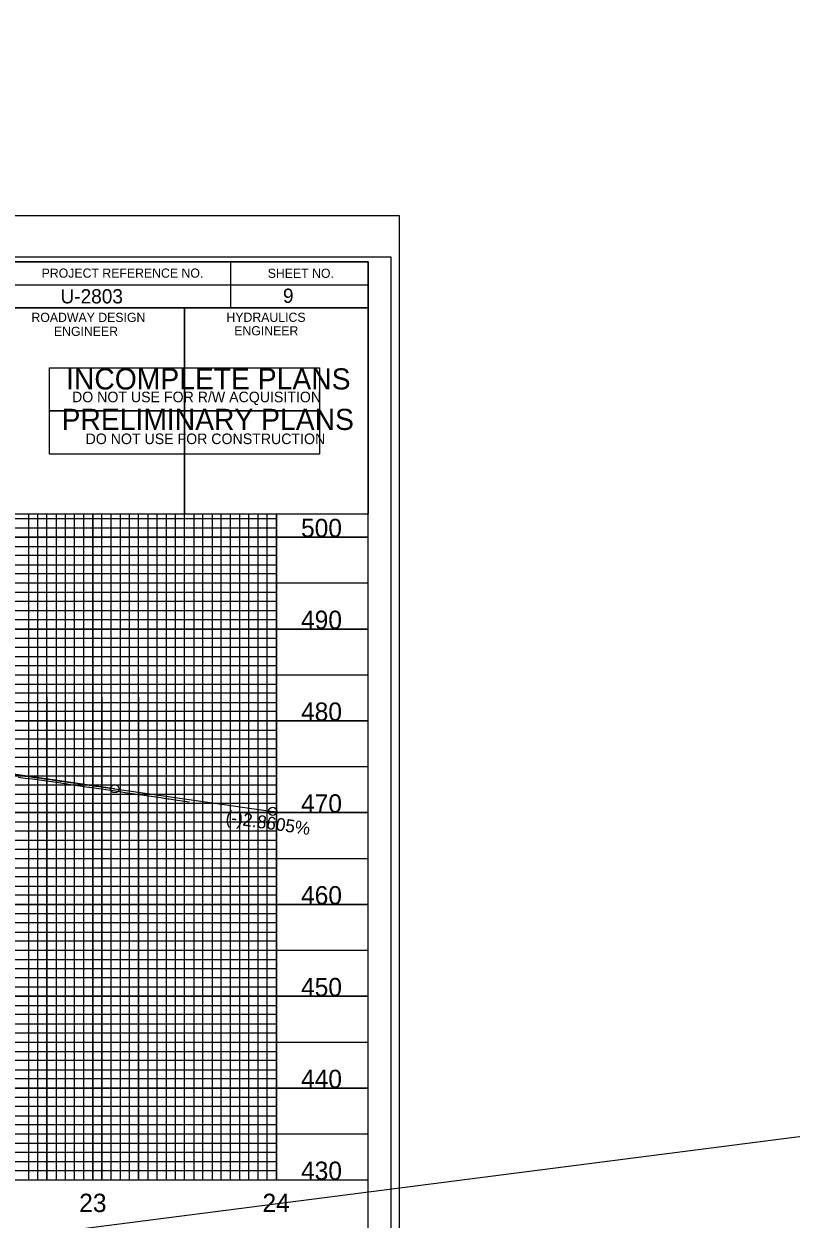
# Model space of a CAD drawing. Extents: x 571503 to 593215, y -77195 to -51828.
# Drawn here: x 582985 to 583403, y -53130 to -52479 of the extents above; entities that cross this region are included whole.
import ezdxf

# ---------------------------------------------------------------- set-up
doc = ezdxf.new("R2010")
doc.units = 0
for name, color, linetype in [('Exist Vertical Profile Ground Line', 7, 'Continuous'), ('Exist Vertical Profile Horizontal Axis Label Major', 7, 'Continuous'), ('Exist Vertical Profile Vertical Axis Label', 7, 'Continuous'), ('Prop PFL Text', 7, 'Continuous'), ('Prop Vertical Profile Curve Label', 7, 'Continuous'), ('Prop Vertical Profile Grade', 7, 'Continuous'), ('Prop Vertical Profile Grade Label', 7, 'Continuous'), ('Prop VPI Label', 7, 'Continuous'), ('Sheet Clip Boundary CELL', 7, 'Continuous'), ('Sheet Data Field CELL', 7, 'Continuous'), ('Sheet DOT Grid CELL', 7, 'Continuous'), ('Sheet Plot Border Inside CELL', 7, 'Continuous'), ('Sheet Plot Border Outside CELL', 7, 'Continuous'), ('Sheet Profile CELL', 7, 'Continuous'), ('Sheet Profile Grid Major CELL', 7, 'Continuous'), ('Sheet Profile Grid Middle CELL', 7, 'Continuous'), ('Sheet Profile Grid Minor CELL', 7, 'Continuous'), ('Sheet Sticker Incomplete CELL', 7, 'Continuous'), ('Sheet Sticker Preliminary CELL', 7, 'Continuous')]:
    doc.layers.add(name, color=color, linetype=linetype)

msp = doc.modelspace()

# ---------------------------------------------------------------- linework, layer by layer
at = {"layer": 'Exist Vertical Profile Ground Line'}
msp.add_lwpolyline([(582981.88, -52889.3), (582985.76, -52889.84), (582989.64, -52890.37), (582993.53, -52890.91), (582997.41, -52891.45), (583000.06, -52891.82), (583001.3, -52892), (583005.18, -52892.55), (583007.78, -52892.92), (583008.24, -52892.98), (583008.57, -52893.03), (583009.07, -52893.1), (583012.95, -52893.66), (583016.83, -52894.22), (583020.36, -52894.73), (583020.72, -52894.78), (583024.6, -52895.35), (583028.49, -52895.92), (583032, -52896.44), (583032.04, -52896.44), (583032.37, -52896.49), (583036.26, -52897.06), (583040.14, -52897.64), (583044.02, -52898.21), (583047.91, -52898.79), (583051.79, -52899.36), (583055.68, -52899.94), (583059.56, -52900.52), (583061.49, -52900.81), (583063.45, -52901.1), (583063.87, -52901.17), (583063.95, -52901.18), (583064, -52901.19), (583065.4, -52901.38), (583067.33, -52901.66), (583071.21, -52902.22), (583075.1, -52902.79)], dxfattribs=at)
at = {"layer": 'Prop PFL Text'}
msp.add_line((571799.62, -54572.45), (593215.36, -51828.37), dxfattribs=at)
at = {"layer": 'Prop Vertical Profile Curve Label'}
for centre in [(583034.51, -52895.68), (583120.51, -52907.98)]:
    msp.add_circle(centre, 2.25, dxfattribs=at)
at = {"layer": 'Prop Vertical Profile Grade'}
msp.add_line((583034.51, -52895.68), (583120.51, -52907.98), dxfattribs=at)
for points in [[(582684.51, -52851.36), (582691.51, -52852.13), (582698.51, -52852.91), (582705.51, -52853.7), (582712.51, -52854.48), (582719.51, -52855.28), (582726.51, -52856.07), (582733.51, -52856.87), (582740.51, -52857.68), (582747.51, -52858.49), (582754.51, -52859.31), (582761.51, -52860.13), (582768.51, -52860.95), (582775.51, -52861.78), (582782.51, -52862.61), (582789.51, -52863.45), (582796.51, -52864.29), (582803.51, -52865.14), (582810.51, -52865.99), (582817.51, -52866.85), (582824.51, -52867.71), (582831.51, -52868.58), (582838.51, -52869.45), (582845.51, -52870.32), (582852.51, -52871.2), (582859.51, -52872.08), (582866.51, -52872.97), (582873.51, -52873.87), (582880.51, -52874.76), (582887.51, -52875.67), (582894.51, -52876.57), (582901.51, -52877.49), (582908.51, -52878.4), (582915.51, -52879.32), (582922.51, -52880.25), (582929.51, -52881.18), (582936.51, -52882.11), (582943.51, -52883.05), (582950.51, -52884), (582957.51, -52884.94), (582964.51, -52885.9), (582971.51, -52886.85), (582978.51, -52887.82), (582985.51, -52888.78), (582992.51, -52889.75), (582999.51, -52890.73), (583006.51, -52891.71), (583013.51, -52892.7), (583020.51, -52893.69), (583027.51, -52894.68), (583034.51, -52895.68)], [(583120.51, -52907.98), (583122.11, -52908.21), (583122.7, -52908.29)]]:
    msp.add_spline(points, degree=3, dxfattribs=at)
at = {"layer": 'Prop VPI Label'}
msp.add_line((583034.51, -52895.68), (582862.23, -52871.04), dxfattribs=at)
at = {"layer": 'Sheet Clip Boundary CELL'}
msp.add_lwpolyline([(581722.51, -52608.7), (581722.51, -53108.7), (583122.51, -53108.7), (583122.51, -52746.25), (582972.46, -52746.25), (582972.46, -52608.7)], close=True, dxfattribs=at)
at = {"layer": 'Sheet DOT Grid CELL'}
for p, q in [((583022.51, -53108.7), (583022.51, -52746.25)), ((583022.51, -53108.7), (583022.51, -52746.25)), ((583072.51, -53108.7), (583072.51, -52746.25)), ((583072.51, -53108.7), (583072.51, -52746.25)), ((583122.51, -53108.7), (583122.51, -52746.25)), ((583122.51, -53108.7), (583122.51, -52746.25)), ((583172.51, -53108.7), (583172.51, -52746.25)), ((581672.51, -52758.7), (583172.51, -52758.7)), ((583172.51, -52758.7), (581672.51, -52758.7)), ((581672.51, -52808.7), (583172.51, -52808.7)), ((583172.51, -52808.7), (581672.51, -52808.7)), ((581672.51, -52858.7), (583172.51, -52858.7)), ((583172.51, -52858.7), (581672.51, -52858.7)), ((581672.51, -52908.7), (583172.51, -52908.7)), ((583172.51, -52908.7), (581672.51, -52908.7)), ((581672.51, -52958.7), (583172.51, -52958.7)), ((583172.51, -52958.7), (581672.51, -52958.7)), ((581672.51, -53008.7), (583172.51, -53008.7)), ((583172.51, -53008.7), (581672.51, -53008.7)), ((581672.51, -53058.7), (583172.51, -53058.7)), ((583172.51, -53058.7), (581672.51, -53058.7))]:
    msp.add_line(p, q, dxfattribs=at)
at = {"layer": 'Sheet Plot Border Inside CELL'}
msp.add_lwpolyline([(581518.51, -53661.25), (583185.01, -53661.25), (583185.01, -52606.15), (581518.51, -52606.15)], close=True, dxfattribs=at)
at = {"layer": 'Sheet Plot Border Outside CELL'}
msp.add_lwpolyline([(581505.51, -53683.7), (583189.51, -53683.7), (583189.51, -52583.7), (581505.51, -52583.7)], close=True, dxfattribs=at)
at = {"layer": 'Sheet Profile CELL'}
for p, q in [((583189.51, -52583.7), (581505.51, -52583.7)), ((583097.51, -52608.75), (583097.51, -52633.75)), ((582972.46, -52621.25), (583172.51, -52621.25)), ((583072.51, -52633.75), (583072.51, -52746.2)), ((581672.51, -53108.7), (583172.51, -53108.7))]:
    msp.add_line(p, q, dxfattribs=at)
for points in [[(583172.51, -52608.7), (581672.51, -52608.7), (581672.51, -53658.7), (583172.51, -53658.7)], [(582972.46, -52608.7), (583172.51, -52608.7), (583172.51, -52633.75), (582972.46, -52633.75)], [(582972.46, -52633.75), (583072.51, -52633.75), (583072.51, -52746.25), (582972.46, -52746.25)], [(583072.51, -52633.75), (583172.51, -52633.75), (583172.51, -52746.25), (583072.51, -52746.25)]]:
    msp.add_lwpolyline(points, close=True, dxfattribs=at)
at = {"layer": 'Sheet Profile Grid Major CELL'}
for points in [[(582522.51, -53108.7), (582572.51, -53108.7), (582572.51, -52608.7), (582622.51, -52608.7), (582622.51, -53108.7), (582672.51, -53108.7), (582672.51, -52608.7), (582722.51, -52608.7), (582722.51, -53108.7), (582772.51, -53108.7), (582772.51, -52608.7), (582822.51, -52608.7), (582822.51, -53108.7), (582872.51, -53108.7), (582872.51, -52608.7), (582922.51, -52608.7), (582922.51, -53108.7), (582972.51, -53108.7), (582972.51, -52608.7), (582998.81, -52608.7)], [(582972.51, -52708.7), (581672.51, -52708.7), (581672.51, -52758.7), (583172.51, -52758.7)], [(583022.51, -52746.25), (583022.51, -53108.7), (583072.51, -53108.7), (583072.51, -53108.7), (583072.51, -52746.25)], [(583122.51, -52746.25), (583122.51, -53108.7), (583172.51, -53108.7), (583172.51, -52758.7)], [(583172.51, -52808.7), (581672.51, -52808.7), (581672.51, -52858.7), (583172.51, -52858.7)], [(583172.51, -52908.7), (581672.51, -52908.7), (581672.51, -52958.7), (583172.51, -52958.7)], [(583172.51, -53008.7), (581672.51, -53008.7), (581672.51, -53008.7), (581672.51, -53058.7), (583172.51, -53058.7)]]:
    msp.add_lwpolyline(points, dxfattribs=at)
at = {"layer": 'Sheet Profile Grid Middle CELL'}
for points in [[(582497.51, -52608.7), (582547.51, -52608.7), (582547.51, -53108.7), (582597.51, -53108.7), (582597.51, -52608.7), (582647.51, -52608.7), (582647.51, -53108.7), (582697.51, -53108.7), (582697.51, -52608.7), (582747.51, -52608.7), (582747.51, -53108.7), (582797.51, -53108.7), (582797.51, -52608.7), (582847.51, -52608.7), (582847.51, -53108.7), (582897.51, -53108.7), (582897.51, -52608.7), (582947.51, -52608.7), (582947.51, -53108.7), (582997.51, -53108.7), (582997.51, -52746.25)], [(582997.51, -52845.9), (582997.51, -53108.7), (583047.51, -53108.7), (583047.51, -52746.25)], [(583047.51, -52845.9), (583047.51, -53108.7), (583097.51, -53108.7), (583097.51, -52746.25)], [(583172.51, -52783.7), (581672.51, -52783.7), (581672.51, -52833.7), (582997.51, -52833.7)], [(582997.51, -52833.7), (583172.51, -52833.7)], [(583172.51, -52883.7), (581672.51, -52883.7), (581672.51, -52933.7), (583172.51, -52933.7)], [(583172.51, -52983.7), (581672.51, -52983.7), (581672.51, -53033.7), (583172.51, -53033.7)], [(583172.51, -53083.7), (581672.51, -53083.7)]]:
    msp.add_lwpolyline(points, dxfattribs=at)
at = {"layer": 'Sheet Profile Grid Minor CELL'}
for p, q in [((583122.51, -52748.7), (581722.51, -52748.7)), ((583122.51, -52753.7), (581722.51, -52753.7)), ((581722.51, -52763.7), (583122.51, -52763.7)), ((583122.51, -52768.7), (581722.51, -52768.7)), ((581722.51, -52773.7), (583122.51, -52773.7)), ((583122.51, -52793.7), (581722.51, -52793.7)), ((581722.51, -52798.7), (583122.51, -52798.7)), ((583122.51, -52818.7), (581722.51, -52818.7)), ((581722.51, -52823.7), (583122.51, -52823.7)), ((583122.51, -52843.7), (581722.51, -52843.7)), ((581722.51, -52848.7), (583122.51, -52848.7)), ((583122.51, -52853.7), (581722.51, -52853.7)), ((581722.51, -52863.7), (583122.51, -52863.7)), ((583122.51, -52868.7), (581722.51, -52868.7)), ((581722.51, -52873.7), (583122.51, -52873.7)), ((583122.51, -52878.7), (581722.51, -52878.7)), ((581722.51, -52888.7), (583122.51, -52888.7)), ((583122.51, -52893.7), (581722.51, -52893.7)), ((581722.51, -52898.7), (583122.51, -52898.7)), ((583122.51, -52903.7), (581722.51, -52903.7)), ((581722.51, -52913.7), (583122.51, -52913.7)), ((583122.51, -52918.7), (581722.51, -52918.7)), ((581722.51, -52923.7), (583122.51, -52923.7)), ((583122.51, -52928.7), (581722.51, -52928.7)), ((581722.51, -52938.7), (583122.51, -52938.7)), ((583122.51, -52943.7), (581722.51, -52943.7)), ((581722.51, -52948.7), (583122.51, -52948.7)), ((583122.51, -52953.7), (581722.51, -52953.7)), ((581722.51, -52963.7), (583122.51, -52963.7)), ((583122.51, -52968.7), (581722.51, -52968.7)), ((581722.51, -52973.7), (583122.51, -52973.7)), ((583122.51, -52978.7), (581722.51, -52978.7)), ((581722.51, -52988.7), (583122.51, -52988.7)), ((583122.51, -52993.7), (581722.51, -52993.7)), ((583122.51, -52998.7), (581722.51, -52998.7)), ((583122.51, -53003.7), (581722.51, -53003.7)), ((581722.51, -53013.7), (583122.51, -53013.7)), ((583122.51, -53018.7), (581722.51, -53018.7)), ((581722.51, -53023.7), (583122.51, -53023.7)), ((583122.51, -53028.7), (581722.51, -53028.7)), ((581722.51, -53038.7), (583122.51, -53038.7)), ((583122.51, -53043.7), (581722.51, -53043.7)), ((581722.51, -53048.7), (583122.51, -53048.7)), ((583122.51, -53053.7), (581722.51, -53053.7)), ((581722.51, -53063.7), (583122.51, -53063.7)), ((583122.51, -53068.7), (581722.51, -53068.7)), ((581722.51, -53073.7), (583122.51, -53073.7)), ((583122.51, -53078.7), (581722.51, -53078.7)), ((581722.51, -53088.7), (583122.51, -53088.7)), ((583122.51, -53093.7), (581722.51, -53093.7)), ((581722.51, -53098.7), (583122.51, -53098.7))]:
    msp.add_line(p, q, dxfattribs=at)
for points in [[(582987.51, -52746.25), (582987.51, -53108.7), (582992.51, -53108.7), (582992.51, -52746.25)], [(583002.51, -52746.25), (583002.51, -53108.7), (583002.51, -53108.7), (583007.51, -53108.7), (583012.51, -53108.7), (583012.51, -52746.25)], [(583007.51, -52746.25), (583007.51, -53108.7)], [(583017.51, -52746.25), (583017.41, -53108.65), (583022.41, -53108.65), (583027.51, -53108.7), (583027.51, -52746.25)], [(583027.51, -52845.9), (583027.51, -53108.7), (583032.51, -53108.7), (583032.51, -52746.25)], [(583037.51, -52746.25), (583037.51, -53108.7), (583042.51, -53108.7), (583042.51, -52746.25)], [(583052.51, -52746.25), (583052.51, -53108.7), (583057.51, -53108.7), (583057.51, -52746.25)], [(583062.51, -52746.25), (583062.51, -53108.7), (583067.51, -53108.7), (583067.51, -52746.25)], [(583077.51, -52746.25), (583077.51, -53108.7), (583082.51, -53108.7), (583082.51, -52746.25)], [(583087.51, -52746.25), (583087.51, -53108.7), (583092.51, -53108.7), (583092.51, -52746.25)], [(583102.51, -52746.25), (583102.51, -53108.7), (583107.51, -53108.7), (583107.51, -52746.25)], [(583112.51, -52746.25), (583112.51, -53108.7), (583117.51, -53108.7), (583117.51, -52746.25)], [(583122.51, -52778.7), (581722.51, -52778.7), (581722.51, -52788.7), (583122.51, -52788.7)], [(583122.51, -52803.7), (581722.51, -52803.7), (581722.51, -52813.7), (583122.51, -52813.7)], [(583122.51, -52828.7), (581722.51, -52828.7), (581722.51, -52838.7), (583122.51, -52838.7)], [(583122.51, -53103.7), (581722.51, -53103.7)]]:
    msp.add_lwpolyline(points, dxfattribs=at)
at = {"layer": 'Sheet Sticker Incomplete CELL'}
msp.add_lwpolyline([(582999.01, -52689.97), (582999.01, -52666.47), (583146.01, -52666.47), (583146.01, -52689.97)], close=True, dxfattribs=at)
at = {"layer": 'Sheet Sticker Preliminary CELL'}
msp.add_lwpolyline([(582999.01, -52713.47), (582999.01, -52689.97), (583146.01, -52689.97), (583146.01, -52713.47)], close=True, dxfattribs=at)

# ---------------------------------------------------------------- texts
at = {"layer": 'Exist Vertical Profile Horizontal Axis Label Major'}
for s, p in [('23', (583015.12, -53126.2)), ('24', (583114.96, -53126.2))]:
    msp.add_text(s, height=10, dxfattribs=at).set_placement(p)
at = {"layer": 'Exist Vertical Profile Vertical Axis Label'}
for s, p in [('500', (583135.94, -52758.7)), ('500', (583135.94, -52758.7)), ('490', (583135.94, -52808.7)), ('490', (583135.94, -52808.7)), ('480', (583135.94, -52858.7)), ('480', (583135.94, -52858.7)), ('470', (583135.94, -52908.7)), ('470', (583135.94, -52908.7)), ('460', (583135.94, -52958.7)), ('460', (583135.94, -52958.7)), ('450', (583135.94, -53008.7)), ('450', (583135.94, -53008.7)), ('440', (583135.94, -53058.7)), ('440', (583135.94, -53058.7)), ('430', (583135.94, -53108.7)), ('430', (583135.94, -53108.7))]:
    msp.add_text(s, height=10, dxfattribs=at).set_placement(p)
at = {"layer": 'Prop Vertical Profile Grade Label'}
msp.add_text('(-)2.8605%', height=7, rotation=351.86057, dxfattribs=at).set_placement((583094.56, -52914.37))
at = {"layer": 'Sheet Data Field CELL'}
for s, p in [('U-2803   ', (583004.96, -52631.39)), ('9  ', (583126.11, -52631.09))]:
    msp.add_text(s, height=7.75, dxfattribs=at).set_placement(p)
at = {"layer": 'Sheet Profile CELL'}
for s, height, p in [('PROJECT REFERENCE NO.', 5.0001, (582994.67, -52617.39)), ('SHEET NO.', 5, (583117.82, -52617.49)), ('ROADWAY DESIGN', 5.0001, (582989.12, -52641.49)), ('HYDRAULICS', 5, (583095.32, -52641.44)), ('ENGINEER', 5, (583001.37, -52649.09)), ('ENGINEER', 5, (583099.57, -52648.79))]:
    msp.add_text(s, height=height, dxfattribs=at).set_placement(p)
at = {"layer": 'Sheet Sticker Incomplete CELL'}
for s, height, p in [('INCOMPLETE PLANS', 11.52, (583007.97, -52678.26)), ('DO NOT USE FOR R/W ACQUISITION', 5.76, (583011.22, -52685.21))]:
    msp.add_text(s, height=height, dxfattribs=at).set_placement(p)
at = {"layer": 'Sheet Sticker Preliminary CELL'}
for s, height, p in [('PRELIMINARY PLANS', 11.52, (583005.52, -52700.31)), ('DO NOT USE FOR CONSTRUCTION', 5.76, (583018.62, -52708.01))]:
    msp.add_text(s, height=height, dxfattribs=at).set_placement(p)

doc.saveas('drawing.dxf')
